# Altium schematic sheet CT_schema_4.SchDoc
size 362 x 192 mm
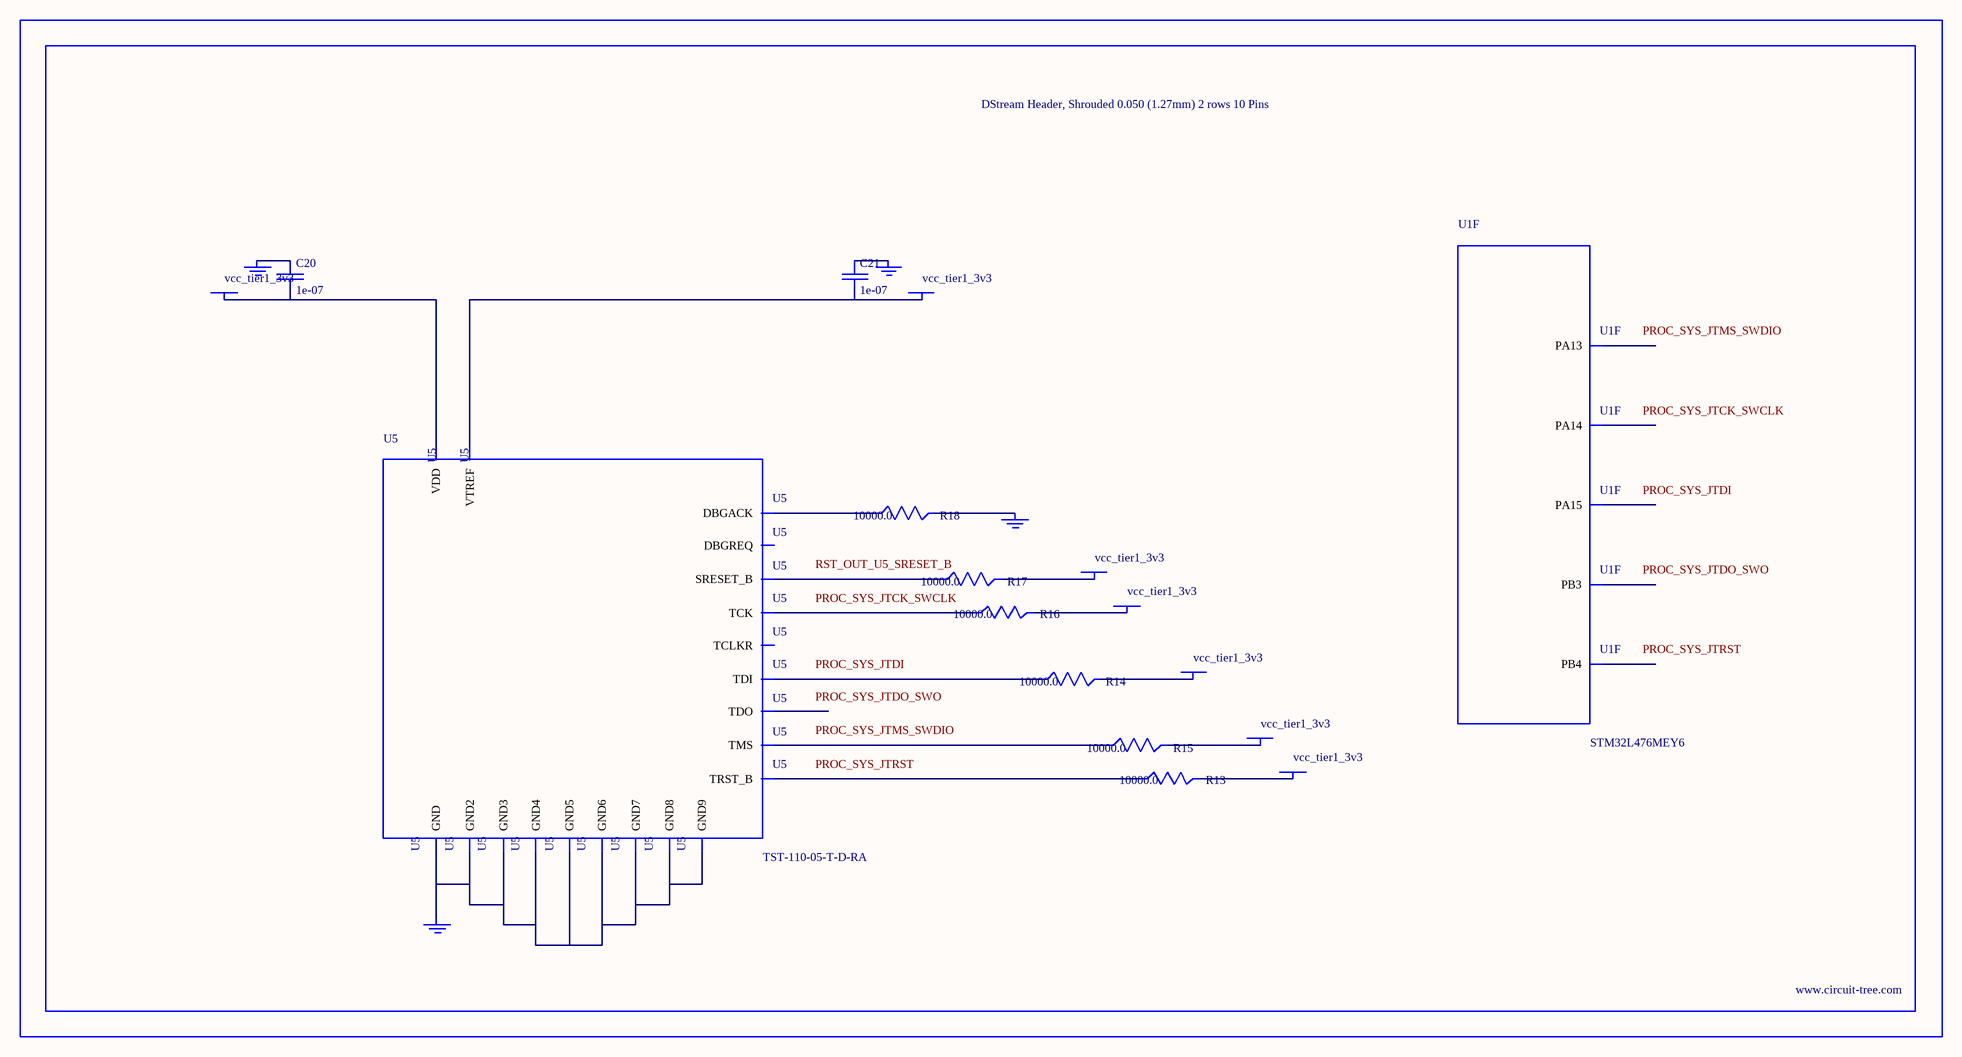
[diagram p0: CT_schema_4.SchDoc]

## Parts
BORDER3  (no value)
C20  1e-07  [C0402]
C21  1e-07  [C0402]
GND_INSTANCE_3_0  (no value)
GND_INSTANCE_3_1  (no value)
GND_INSTANCE_3_2  (no value)
GND_INSTANCE_3_3  (no value)
POWER_INSTANCE_3_0  vcc_tier1_3v3
POWER_INSTANCE_3_1  vcc_tier1_3v3
POWER_INSTANCE_3_2  vcc_tier1_3v3
POWER_INSTANCE_3_3  vcc_tier1_3v3
POWER_INSTANCE_3_4  vcc_tier1_3v3
POWER_INSTANCE_3_5  vcc_tier1_3v3
POWER_INSTANCE_3_6  vcc_tier1_3v3
R13  10000.0  [R0603]
R14  10000.0  [R0603]
R15  10000.0  [R0603]
R16  10000.0  [R0603]
R17  10000.0  [R0603]
R18  10000.0  [R0603]
U1  STM32L476MEY6  [WLCSP81]  (part F of 9)
U5  TST-110-05-T-D-RA  [TST-110-05-T-D-RA]

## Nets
NetC20_1: C20.1 GND_INSTANCE_3_1.0(GND)
NetC20_2: C20.2 POWER_INSTANCE_3_1.0(PWR) U5.2(VDD)
NetC21_1: C21.1 GND_INSTANCE_3_0.0(GND)
NetC21_2: C21.2 POWER_INSTANCE_3_0.0(PWR) U5.1(VTREF)
NetGND_INSTANCE_3_2_0: GND_INSTANCE_3_2.0(GND) R18.2
NetGND_INSTANCE_3_3_0: GND_INSTANCE_3_3.0(GND) U5.4(GND) U5.6(GND2) U5.8(GND3) U5.10(GND4) U5.12(GND5) U5.14(GND6) U5.16(GND7) U5.18(GND8) U5.20(GND9)
NetPOWER_INSTANCE_3_2_0: POWER_INSTANCE_3_2.0(PWR) R13.2
NetPOWER_INSTANCE_3_3_0: POWER_INSTANCE_3_3.0(PWR) R14.2
NetPOWER_INSTANCE_3_4_0: POWER_INSTANCE_3_4.0(PWR) R15.2
NetPOWER_INSTANCE_3_5_0: POWER_INSTANCE_3_5.0(PWR) R16.2
NetPOWER_INSTANCE_3_6_0: POWER_INSTANCE_3_6.0(PWR) R17.2
NetR13_1: R13.1 U5.3(TRST_B)
NetR14_1: R14.1 U5.5(TDI)
NetR15_1: R15.1 U5.7(TMS)
NetR16_1: R16.1 U5.9(TCK)
NetR17_1: R17.1 U5.15(SRESET_B)
NetR18_1: R18.1 U5.19(DBGACK)

Not connected (* = marked no-connect by the designer): U1 A2(PA15) A6(PB3) B2(PA14) C2(PA13) C6(PB4); U5 11(TCLKR) 13(TDO) 17(DBGREQ)

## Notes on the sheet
- Labels drawn without touching a wire or pin: PROC_SYS_JTCK_SWCLK, PROC_SYS_JTDI, PROC_SYS_JTDO_SWO, PROC_SYS_JTMS_SWDIO, PROC_SYS_JTRST, RST_OUT_U5_SRESET_B

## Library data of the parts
BORDER3 = BORDER_PAGE3
C20 C21 = C0402C104K3RACTU
GND_INSTANCE_3_0-GND_INSTANCE_3_3 = GND
POWER_INSTANCE_3_0-POWER_INSTANCE_3_6 = PWR
R13-R18 = RC0603JR-0710KL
